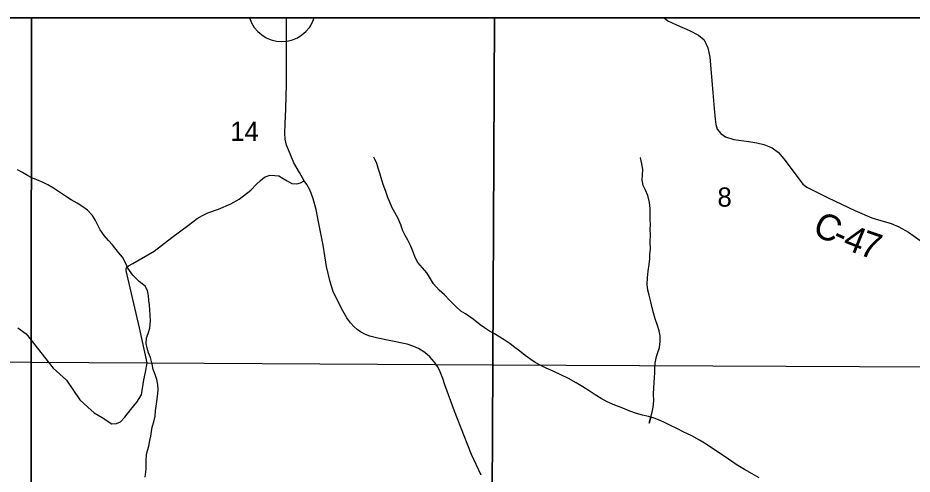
# Model space of a CAD drawing. Extents: x 2.1 to 8.9, y 14.1 to 20.9.
# Drawn here: x 3.51 to 5.459, y 19.907 to 20.9 of the extents above; entities that cross this region are included whole.
import ezdxf

# ---------------------------------------------------------------- set-up
doc = ezdxf.new("R2010")
doc.units = 0
for name, color, linetype in [('Default', 7, 'Continuous'), ('GM_X_City_Street', 7, 'Continuous'), ('GM_X_County_Road_Text', 7, 'Continuous'), ('GM_X_Interchange_Ramps', 7, 'Continuous'), ('GM_X_Minor_River', 7, 'Continuous'), ('GM_X_Rail_Line_Text', 7, 'Continuous'), ('GM_X_State_Shield', 7, 'Continuous'), ('SH_Cut_Line', 7, 'Continuous'), ('SH_Data', 7, 'Continuous'), ('TX_P_Misc', 7, 'Continuous')]:
    doc.layers.add(name, color=color, linetype=linetype)

msp = doc.modelspace()

# ---------------------------------------------------------------- linework, layer by layer
at = {"layer": 'Default'}
for p, q in [((7.8225, 20.9), (2.1, 20.9)), ((3.5394, 20.9), (2.4251, 20.9)), ((3.5394, 20.9), (3.5383, 20.1501)), ((3.5383, 20.1501), (3.5394, 20.9)), ((4.5485, 20.9), (3.5394, 20.9)), ((4.1557, 20.9), (4.0142, 20.9)), ((4.5449, 20.1449), (4.5485, 20.9)), ((4.5485, 20.9), (4.5449, 20.1449)), ((5.558, 20.9), (4.5485, 20.9)), ((2.5263, 20.1669), (3.5383, 20.1501)), ((3.5383, 20.1501), (4.5449, 20.1449)), ((4.5449, 20.1449), (5.5506, 20.1397))]:
    msp.add_line(p, q, dxfattribs=at)
msp.add_arc((4.085, 20.923), 0.0744, 198.008, 341.992, dxfattribs=at)
at = {"layer": 'GM_X_City_Street'}
for p, q in [((4.0296, 20.5379), (4.0385, 20.546)), ((4.0385, 20.546), (4.0469, 20.5532)), ((4.0469, 20.5532), (4.0588, 20.5573)), ((4.0588, 20.5573), (4.07, 20.5572)), ((4.07, 20.5572), (4.0782, 20.5558)), ((4.0782, 20.5558), (4.0879, 20.5503)), ((4.0879, 20.5503), (4.0969, 20.5451)), ((4.0969, 20.5451), (4.1066, 20.5398)), ((4.126, 20.5408), (4.1339, 20.5455)), ((3.9919, 20.5054), (4.0175, 20.5252)), ((4.0175, 20.5252), (4.0296, 20.5379)), ((4.1066, 20.5398), (4.1174, 20.5387)), ((4.1174, 20.5387), (4.126, 20.5408)), ((3.9469, 20.4837), (3.9737, 20.4949)), ((3.9737, 20.4949), (3.9919, 20.5054)), ((3.9007, 20.4636), (3.9122, 20.47)), ((3.9122, 20.47), (3.9235, 20.4753)), ((3.9235, 20.4753), (3.9469, 20.4837)), ((3.8454, 20.4222), (3.8817, 20.4487)), ((3.8817, 20.4487), (3.9007, 20.4636)), ((3.807, 20.3924), (3.8454, 20.4222)), ((3.7604, 20.3656), (3.807, 20.3924)), ((3.7456, 20.3499), (3.746, 20.354)), ((3.7526, 20.3219), (3.7456, 20.3499)), ((3.746, 20.354), (3.7475, 20.3571)), ((3.7475, 20.3571), (3.7509, 20.3599)), ((3.7509, 20.3599), (3.7604, 20.3656)), ((3.7751, 20.225), (3.7526, 20.3219)), ((3.5094, 20.2253), (3.528, 20.212)), ((3.7913, 20.1491), (3.7751, 20.225)), ((3.528, 20.212), (3.5866, 20.1372)), ((3.5866, 20.1372), (3.6157, 20.1109)), ((3.7882, 20.1284), (3.7913, 20.1491)), ((3.7844, 20.1121), (3.7882, 20.1284)), ((3.6157, 20.1109), (3.6448, 20.0687)), ((3.7789, 20.0795), (3.7844, 20.1121)), ((3.7693, 20.063), (3.7789, 20.0795)), ((3.6448, 20.0687), (3.6623, 20.0523)), ((3.756, 20.0471), (3.7693, 20.063)), ((3.6623, 20.0523), (3.6756, 20.0404)), ((3.6756, 20.0404), (3.6932, 20.03)), ((3.7427, 20.0309), (3.756, 20.0471)), ((3.6932, 20.03), (3.7142, 20.0159)), ((3.7247, 20.0166), (3.7337, 20.0202)), ((3.7337, 20.0202), (3.7427, 20.0309)), ((3.7142, 20.0159), (3.7247, 20.0166))]:
    msp.add_line(p, q, dxfattribs=at)
at = {"layer": 'GM_X_Interchange_Ramps'}
for p, q in [((2.5263, 20.1669), (3.5383, 20.1501)), ((3.5383, 20.1501), (3.5387, 19.1524)), ((3.5387, 19.1524), (3.5383, 20.1501)), ((3.5383, 20.1501), (4.5449, 20.1449)), ((4.5449, 20.1449), (4.5388, 19.1444)), ((4.5388, 19.1444), (4.5449, 20.1449)), ((4.5449, 20.1449), (5.5506, 20.1397))]:
    msp.add_line(p, q, dxfattribs=at)
at = {"layer": 'GM_X_Rail_Line_Text'}
for p, q in [((4.0951, 20.8662), (4.0951, 20.9)), ((4.0954, 20.7971), (4.0951, 20.8662)), ((4.0954, 20.7554), (4.0954, 20.7971)), ((4.0936, 20.7023), (4.0954, 20.7554)), ((4.0923, 20.6697), (4.0936, 20.7023)), ((4.0918, 20.6487), (4.0923, 20.6697)), ((4.0923, 20.636), (4.0918, 20.6487)), ((4.0955, 20.6228), (4.0923, 20.636)), ((4.1034, 20.6043), (4.0955, 20.6228)), ((4.1113, 20.5844), (4.1034, 20.6043)), ((4.1236, 20.5634), (4.1113, 20.5844)), ((4.1339, 20.5455), (4.1236, 20.5634)), ((4.1395, 20.5372), (4.1339, 20.5455)), ((4.1454, 20.5269), (4.1395, 20.5372)), ((4.1486, 20.5181), (4.1454, 20.5269)), ((4.1534, 20.5062), (4.1486, 20.5181)), ((4.1597, 20.4828), (4.1534, 20.5062)), ((4.1649, 20.4558), (4.1597, 20.4828)), ((4.1752, 20.4055), (4.1649, 20.4558)), ((4.1823, 20.359), (4.1752, 20.4055)), ((4.1903, 20.3252), (4.1823, 20.359)), ((4.1966, 20.3044), (4.1903, 20.3252)), ((4.2099, 20.2771), (4.1966, 20.3044)), ((4.2181, 20.2622), (4.2099, 20.2771)), ((4.2264, 20.2472), (4.2181, 20.2622)), ((4.2347, 20.236), (4.2264, 20.2472)), ((4.2426, 20.2274), (4.2347, 20.236)), ((4.2489, 20.2218), (4.2426, 20.2274)), ((4.2563, 20.2167), (4.2489, 20.2218)), ((4.2676, 20.211), (4.2563, 20.2167)), ((4.277, 20.2071), (4.2676, 20.211)), ((4.2943, 20.2029), (4.277, 20.2071)), ((4.3187, 20.1979), (4.2943, 20.2029)), ((4.3583, 20.1896), (4.3187, 20.1979)), ((4.3728, 20.1848), (4.3583, 20.1896)), ((4.3831, 20.1801), (4.3728, 20.1848)), ((4.3965, 20.1717), (4.3831, 20.1801)), ((4.4079, 20.1621), (4.3965, 20.1717)), ((4.4181, 20.1505), (4.4079, 20.1621)), ((4.4245, 20.141), (4.4181, 20.1505)), ((4.4284, 20.1327), (4.4245, 20.141)), ((4.4358, 20.115), (4.4284, 20.1327)), ((4.4405, 20.1008), (4.4358, 20.115)), ((4.4611, 20.0437), (4.4405, 20.1008)), ((4.4823, 19.9901), (4.4611, 20.0437)), ((4.4987, 19.9491), (4.4823, 19.9901)), ((4.5194, 19.9047), (4.4987, 19.9491))]:
    msp.add_line(p, q, dxfattribs=at)
at = {"layer": 'GM_X_State_Shield'}
for p, q in [((4.9181, 20.9), (4.9265, 20.8933)), ((4.9265, 20.8933), (4.9456, 20.8848)), ((4.9456, 20.8848), (4.9739, 20.8727)), ((4.9739, 20.8727), (4.9933, 20.8625)), ((4.9933, 20.8625), (5.0055, 20.8526)), ((5.0055, 20.8526), (5.0136, 20.835)), ((5.0136, 20.835), (5.0181, 20.8148)), ((5.0181, 20.8148), (5.0248, 20.7375)), ((5.0248, 20.7375), (5.0275, 20.7027)), ((5.0275, 20.7027), (5.0295, 20.6794)), ((5.0295, 20.6794), (5.0307, 20.6679)), ((5.0307, 20.6679), (5.0341, 20.6576)), ((5.0341, 20.6576), (5.042, 20.6481)), ((5.042, 20.6481), (5.0523, 20.641)), ((5.0523, 20.641), (5.0703, 20.6354)), ((5.0703, 20.6354), (5.1027, 20.6307)), ((5.1027, 20.6307), (5.1207, 20.6279)), ((5.1207, 20.6279), (5.1359, 20.6241)), ((5.1359, 20.6241), (5.1537, 20.6171)), ((5.1537, 20.6171), (5.1678, 20.6066)), ((5.1678, 20.6066), (5.1794, 20.5932)), ((5.1794, 20.5932), (5.1972, 20.5691)), ((5.1972, 20.5691), (5.2206, 20.5378)), ((5.2206, 20.5378), (5.2293, 20.5313)), ((5.2293, 20.5313), (5.2756, 20.5081)), ((5.2756, 20.5081), (5.3338, 20.4804)), ((5.3338, 20.4804), (5.3711, 20.4649)), ((5.3711, 20.4649), (5.3907, 20.4587)), ((5.3907, 20.4587), (5.4131, 20.4521)), ((5.4131, 20.4521), (5.4296, 20.4454)), ((5.4296, 20.4454), (5.4508, 20.4332)), ((5.4508, 20.4332), (5.5114, 20.3899))]:
    msp.add_line(p, q, dxfattribs=at)
at = {"layer": 'SH_Cut_Line'}
msp.add_line((7.8225, 20.9), (2.1, 20.9), dxfattribs=at)
at = {"layer": 'SH_Data'}
msp.add_line((2.1, 20.9), (8.9, 20.9), dxfattribs=at)
msp.add_line((2.1, 20.9), (8.9, 20.9), dxfattribs=at)
at = {"layer": 'TX_P_Misc'}
for p, q in [((4.2871, 20.5936), (4.2854, 20.5969)), ((4.292, 20.5831), (4.2871, 20.5936)), ((4.8665, 20.595), (4.866, 20.5957)), ((4.8695, 20.5825), (4.8665, 20.595)), ((3.5196, 20.5635), (3.5088, 20.5693)), ((4.2953, 20.5725), (4.292, 20.5831)), ((4.2983, 20.5616), (4.2953, 20.5725)), ((4.8722, 20.5697), (4.8695, 20.5825)), ((4.8714, 20.5583), (4.8722, 20.5697)), ((3.5305, 20.557), (3.5196, 20.5635)), ((3.5401, 20.552), (3.5305, 20.557)), ((3.5509, 20.5474), (3.5401, 20.552)), ((3.5648, 20.5414), (3.5509, 20.5474)), ((4.3013, 20.5518), (4.2983, 20.5616)), ((4.3059, 20.5371), (4.3013, 20.5518)), ((4.8706, 20.5465), (4.8714, 20.5583)), ((4.8729, 20.5351), (4.8706, 20.5465)), ((3.5752, 20.5367), (3.5648, 20.5414)), ((3.5872, 20.5295), (3.5752, 20.5367)), ((3.6004, 20.5208), (3.5872, 20.5295)), ((4.3114, 20.5217), (4.3059, 20.5371)), ((4.8778, 20.525), (4.8729, 20.5351)), ((3.6136, 20.5117), (3.6004, 20.5208)), ((3.626, 20.5041), (3.6136, 20.5117)), ((4.3163, 20.5089), (4.3114, 20.5217)), ((4.3205, 20.4988), (4.3163, 20.5089)), ((4.8831, 20.5134), (4.8778, 20.525)), ((4.8866, 20.4979), (4.8831, 20.5134)), ((3.6388, 20.4965), (3.626, 20.5041)), ((3.6493, 20.4904), (3.6388, 20.4965)), ((3.6613, 20.4816), (3.6493, 20.4904)), ((4.3258, 20.4864), (4.3205, 20.4988)), ((4.331, 20.4763), (4.3258, 20.4864)), ((4.8878, 20.485), (4.8866, 20.4979)), ((3.672, 20.4698), (3.6613, 20.4816)), ((3.6792, 20.4586), (3.672, 20.4698)), ((4.3383, 20.4632), (4.331, 20.4763)), ((4.8878, 20.4732), (4.8878, 20.485)), ((4.8878, 20.4611), (4.8878, 20.4732)), ((3.6836, 20.4489), (3.6792, 20.4586)), ((3.6889, 20.4388), (3.6836, 20.4489)), ((4.3444, 20.4494), (4.3383, 20.4632)), ((4.349, 20.4362), (4.3444, 20.4494)), ((4.8885, 20.4512), (4.8878, 20.4611)), ((4.8881, 20.4394), (4.8885, 20.4512)), ((3.6977, 20.4261), (3.6889, 20.4388)), ((4.3535, 20.4261), (4.349, 20.4362)), ((4.8884, 20.428), (4.8881, 20.4394)), ((4.8882, 20.4116), (4.8884, 20.428)), ((3.7075, 20.4154), (3.6977, 20.4261)), ((3.7158, 20.4058), (3.7075, 20.4154)), ((4.3595, 20.416), (4.3535, 20.4261)), ((4.366, 20.4033), (4.3595, 20.416)), ((4.8883, 20.3968), (4.8882, 20.4116)), ((3.7292, 20.3895), (3.7158, 20.4058)), ((3.7379, 20.3791), (3.7292, 20.3895)), ((4.3722, 20.3886), (4.366, 20.4033)), ((4.8875, 20.3854), (4.8883, 20.3968)), ((3.7448, 20.3652), (3.7379, 20.3791)), ((4.3756, 20.3781), (4.3722, 20.3886)), ((4.3816, 20.3676), (4.3756, 20.3781)), ((4.8855, 20.3629), (4.887, 20.3751)), ((4.887, 20.3751), (4.8875, 20.3854)), ((3.7493, 20.3551), (3.7448, 20.3652)), ((3.7601, 20.3402), (3.7493, 20.3551)), ((4.3919, 20.3558), (4.3816, 20.3676)), ((4.4009, 20.3451), (4.3919, 20.3558)), ((4.8837, 20.3484), (4.8855, 20.3629)), ((3.7738, 20.3262), (3.7601, 20.3402)), ((4.4069, 20.3354), (4.4009, 20.3451)), ((4.4158, 20.3208), (4.4069, 20.3354)), ((4.8816, 20.3194), (4.8819, 20.3343)), ((4.8819, 20.3343), (4.8837, 20.3484)), ((3.7874, 20.316), (3.7738, 20.3262)), ((3.7923, 20.3062), (3.7874, 20.316)), ((4.4283, 20.3075), (4.4158, 20.3208)), ((4.8827, 20.3073), (4.8816, 20.3194)), ((3.7942, 20.2949), (3.7923, 20.3062)), ((3.7953, 20.2847), (3.7942, 20.2949)), ((4.4397, 20.2968), (4.4283, 20.3075)), ((4.4503, 20.2858), (4.4397, 20.2968)), ((4.8857, 20.296), (4.8827, 20.3073)), ((4.8892, 20.2816), (4.8857, 20.296)), ((3.7963, 20.2752), (3.7953, 20.2847)), ((3.797, 20.2638), (3.7963, 20.2752)), ((4.4637, 20.2721), (4.4503, 20.2858)), ((4.475, 20.2618), (4.4637, 20.2721)), ((4.8919, 20.2688), (4.8892, 20.2816)), ((3.7981, 20.2536), (3.797, 20.2638)), ((3.7989, 20.2407), (3.7981, 20.2536)), ((4.4851, 20.2557), (4.475, 20.2618)), ((4.5022, 20.2444), (4.4851, 20.2557)), ((4.8949, 20.2575), (4.8919, 20.2688)), ((4.8987, 20.2447), (4.8949, 20.2575)), ((3.7975, 20.2243), (3.7989, 20.2407)), ((4.517, 20.2316), (4.5022, 20.2444)), ((4.9041, 20.2304), (4.8987, 20.2447)), ((3.7937, 20.2131), (3.7975, 20.2243)), ((4.5271, 20.225), (4.517, 20.2316)), ((4.5376, 20.2182), (4.5271, 20.225)), ((4.5488, 20.2124), (4.5376, 20.2182)), ((4.9075, 20.2187), (4.9041, 20.2304)), ((4.9094, 20.2078), (4.9075, 20.2187)), ((3.7891, 20.1913), (3.7902, 20.2031)), ((3.7902, 20.2031), (3.7937, 20.2131)), ((4.5601, 20.2052), (4.5488, 20.2124)), ((4.5698, 20.199), (4.5601, 20.2052)), ((4.5826, 20.1907), (4.5698, 20.199)), ((4.9079, 20.1826), (4.9098, 20.1952)), ((4.9098, 20.1952), (4.9094, 20.2078)), ((3.7913, 20.1811), (3.7891, 20.1913)), ((3.7946, 20.171), (3.7913, 20.1811)), ((4.5931, 20.1826), (4.5826, 20.1907)), ((4.604, 20.1742), (4.5931, 20.1826)), ((4.9017, 20.1626), (4.9079, 20.1826)), ((3.7984, 20.1604), (3.7946, 20.171)), ((3.8023, 20.1461), (3.7984, 20.1604)), ((4.6157, 20.1647), (4.604, 20.1742)), ((4.6278, 20.156), (4.6157, 20.1647)), ((4.6375, 20.1498), (4.6278, 20.156)), ((4.8987, 20.1485), (4.9017, 20.1626)), ((3.8045, 20.1348), (3.8023, 20.1461)), ((4.6479, 20.144), (4.6375, 20.1498)), ((4.661, 20.1372), (4.6479, 20.144)), ((4.6765, 20.1309), (4.661, 20.1372)), ((4.8982, 20.1272), (4.8983, 20.1382)), ((4.8983, 20.1382), (4.8987, 20.1485)), ((3.8087, 20.1235), (3.8045, 20.1348)), ((3.8124, 20.113), (3.8087, 20.1235)), ((4.6934, 20.123), (4.6765, 20.1309)), ((4.71, 20.1148), (4.6934, 20.123)), ((4.8958, 20.0948), (4.8974, 20.1169)), ((4.8974, 20.1169), (4.8982, 20.1272)), ((3.8147, 20.1016), (3.8124, 20.113)), ((3.8154, 20.091), (3.8147, 20.1016)), ((4.7263, 20.1054), (4.71, 20.1148)), ((4.741, 20.0968), (4.7263, 20.1054)), ((4.7546, 20.0877), (4.741, 20.0968)), ((3.8124, 20.065), (3.8145, 20.0815)), ((3.8145, 20.0815), (3.8154, 20.091)), ((4.7678, 20.079), (4.7546, 20.0877)), ((4.781, 20.071), (4.7678, 20.079)), ((4.8955, 20.0807), (4.8958, 20.0948)), ((4.8959, 20.0666), (4.8955, 20.0807)), ((3.8108, 20.0547), (3.8124, 20.065)), ((4.7945, 20.0638), (4.781, 20.071)), ((4.8107, 20.0571), (4.7945, 20.0638)), ((4.8945, 20.0522), (4.8959, 20.0666)), ((3.8092, 20.033), (3.8096, 20.0444)), ((3.8096, 20.0444), (3.8108, 20.0547)), ((4.8284, 20.0501), (4.8107, 20.0571)), ((4.8438, 20.0441), (4.8284, 20.0501)), ((4.858, 20.0388), (4.8438, 20.0441)), ((4.8715, 20.0351), (4.858, 20.0388)), ((4.8884, 20.0288), (4.8922, 20.0414)), ((4.8922, 20.0414), (4.8945, 20.0522)), ((3.8024, 20.0092), (3.8058, 20.0204)), ((3.8058, 20.0204), (3.8092, 20.033)), ((4.8845, 20.0321), (4.8715, 20.0351)), ((4.8968, 20.0283), (4.8845, 20.0321)), ((4.8897, 20.0305), (4.8857, 20.0177)), ((4.8857, 20.0177), (4.8884, 20.0288)), ((4.9095, 20.0233), (4.8968, 20.0283)), ((4.9191, 20.0191), (4.9095, 20.0233)), ((4.9295, 20.0141), (4.9191, 20.0191)), ((3.7996, 19.9894), (3.8011, 19.9997)), ((3.8011, 19.9997), (3.8024, 20.0092)), ((4.9473, 20.0051), (4.9295, 20.0141)), ((4.9616, 19.998), (4.9473, 20.0051)), ((3.7949, 19.9679), (3.7976, 19.9798)), ((3.7976, 19.9798), (3.7996, 19.9894)), ((4.979, 19.9898), (4.9616, 19.998)), ((4.9956, 19.9804), (4.979, 19.9898)), ((5.0103, 19.9721), (4.9956, 19.9804)), ((3.7922, 19.9583), (3.7949, 19.9679)), ((5.0262, 19.9612), (5.0103, 19.9721)), ((5.0425, 19.9503), (5.0262, 19.9612)), ((3.7894, 19.9373), (3.7898, 19.9484)), ((3.7898, 19.9484), (3.7922, 19.9583)), ((5.0589, 19.9394), (5.0425, 19.9503)), ((3.7893, 19.9274), (3.7894, 19.9373)), ((3.7896, 19.9176), (3.7893, 19.9274)), ((5.0756, 19.9278), (5.0589, 19.9394)), ((5.0938, 19.917), (5.0756, 19.9278)), ((3.7871, 19.9004), (3.7896, 19.9176)), ((5.1104, 19.9072), (5.0938, 19.917)), ((5.1255, 19.8986), (5.1104, 19.9072))]:
    msp.add_line(p, q, dxfattribs=at)

# ---------------------------------------------------------------- texts
at = {"layer": 'GM_X_County_Road_Text'}
for s, height, p in [('14', 0.04186, (3.9726, 20.6322)), ('8', 0.0419, (5.0346, 20.489))]:
    msp.add_text(s, height=height, rotation=0, dxfattribs=at).set_placement(p)
at = {"layer": 'GM_X_Minor_River'}
for s, rotation, p in [('C', 334.6746, (5.2387, 20.4304)), ('-', 335.7262, (5.2816, 20.4101)), ('4', 337.8731, (5.3048, 20.3997)), ('7', 341.3807, (5.3405, 20.3853))]:
    msp.add_text(s, height=0.0568, rotation=rotation, dxfattribs=at).set_placement(p)

doc.saveas('drawing.dxf')
